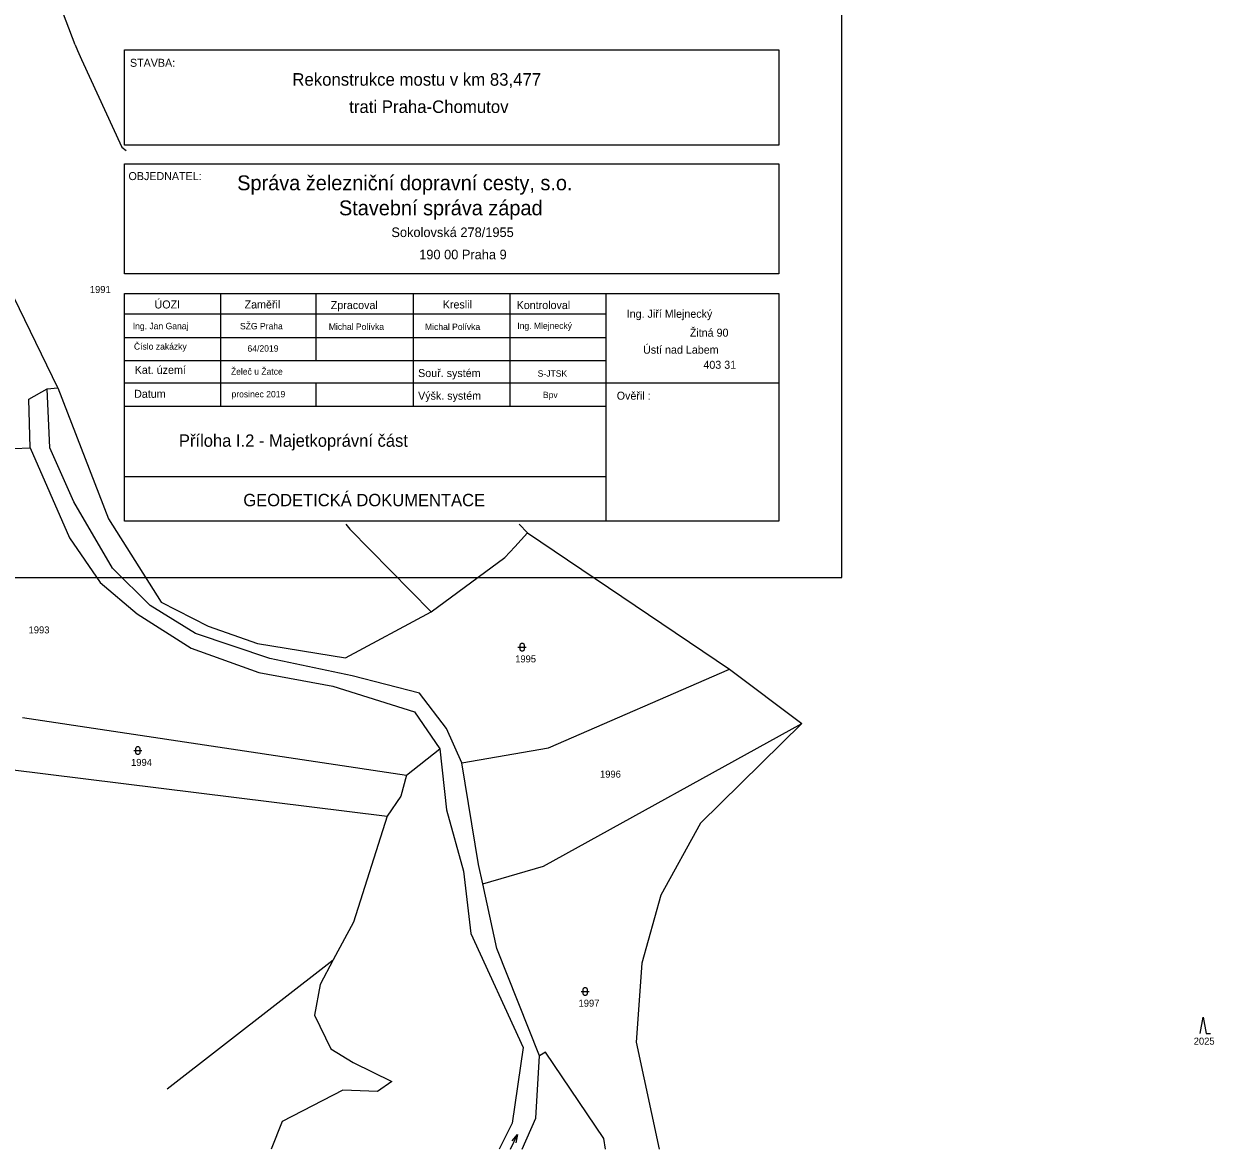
# Model space of a CAD drawing. Extents: x -801853 to -800578, y -1017479 to -1016338.
# Drawn here: x -800916.5 to -800627.9, y -1017477.7 to -1017204.8 of the extents above; entities that cross this region are included whole.
import ezdxf

# ---------------------------------------------------------------- set-up
doc = ezdxf.new("R2010")
doc.units = 0
for name, color, linetype in [('Default', 7, 'Continuous'), ('KN_HRANICE', 7, 'Continuous'), ('KN_KULTURY', 7, 'Continuous'), ('KN_PARCELY', 7, 'Continuous'), ('LEGENDA', 7, 'Continuous'), ('tabulka', 7, 'Continuous')]:
    doc.layers.add(name, color=color, linetype=linetype)

# ---------------------------------------------------------------- blocks, each defined once
blk = doc.blocks.new('308')
at = {"layer": 'Default'}
blk.add_lwpolyline([(-0.75, 0), (0, 4), (0.75, 0), (1.75, 0)], dxfattribs=at)
blk = doc.blocks.new('316')
at = {"layer": 'Default'}
for points in [[(-1, 1), (0.27, 1), (1, 1)], [(-0.5, 1.5), (-0.4, 1.79), (-0.15, 1.97), (0.16, 1.97), (0.41, 1.79), (0.51, 1.5), (0.51, 0.5), (0.41, 0.21), (0.16, 0.03), (-0.15, 0.03), (-0.4, 0.21), (-0.5, 0.5), (-0.5, 1.5)]]:
    blk.add_lwpolyline(points, dxfattribs=at)

msp = doc.modelspace()

# ---------------------------------------------------------------- linework, layer by layer
at = {"layer": 'KN_HRANICE'}
for p, q in [((-800904.03, -1017209.93), (-800916.2, -1017177.92)), ((-800904.03, -1017209.93), (-800903.5, -1017211.33)), ((-800903.5, -1017211.33), (-800902.5, -1017213.51)), ((-800902.5, -1017213.51), (-800892.76, -1017234.71)), ((-800892.76, -1017234.71), (-800891.71, -1017235.57)), ((-800908.25, -1017293.09), (-800925.53, -1017257.6)), ((-800915.3, -1017295.86), (-800910.8, -1017293.37)), ((-800910.8, -1017293.37), (-800908.25, -1017293.09)), ((-800910.14, -1017307.62), (-800910.8, -1017293.37)), ((-800908.25, -1017293.09), (-800895.98, -1017324.86)), ((-800914.93, -1017307.65), (-800915.3, -1017295.86)), ((-800925.36, -1017308.04), (-800914.93, -1017307.65)), ((-800914.93, -1017307.65), (-800905.45, -1017329.47)), ((-800904.4, -1017320.71), (-800910.14, -1017307.62)), ((-800894.96, -1017336.82), (-800904.4, -1017320.71)), ((-800895.98, -1017324.86), (-800883.2, -1017345.04)), ((-800838.41, -1017326.15), (-800837.42, -1017327.39)), ((-800837.42, -1017327.39), (-800817.72, -1017347.38)), ((-800797.47, -1017331.62), (-800794.33, -1017328.28)), ((-800796.41, -1017326.15), (-800794.33, -1017328.28)), ((-800794.33, -1017328.28), (-800745.35, -1017361.29)), ((-800905.45, -1017329.47), (-800897.94, -1017340.24)), ((-800817.72, -1017347.38), (-800799.89, -1017334.2)), ((-800799.89, -1017334.2), (-800797.47, -1017331.62)), ((-800885.82, -1017345.89), (-800894.96, -1017336.82)), ((-800897.94, -1017340.24), (-800888.98, -1017347.84)), ((-800874.85, -1017352.61), (-800885.82, -1017345.89)), ((-800883.2, -1017345.04), (-800871.81, -1017350.85)), ((-800888.98, -1017347.84), (-800875.89, -1017356.2)), ((-800838.46, -1017358.55), (-800817.72, -1017347.38)), ((-800871.81, -1017350.85), (-800859.86, -1017355.03)), ((-800856.81, -1017358.7), (-800874.85, -1017352.61)), ((-800875.89, -1017356.2), (-800859.52, -1017362.06)), ((-800859.86, -1017355.03), (-800838.46, -1017358.55)), ((-800836.88, -1017362.87), (-800856.81, -1017358.7)), ((-800859.52, -1017362.06), (-800841.58, -1017365.44)), ((-800820.52, -1017367.14), (-800836.88, -1017362.87)), ((-800789.24, -1017380.33), (-800745.35, -1017361.29)), ((-800745.35, -1017361.29), (-800727.83, -1017374.48)), ((-800841.58, -1017365.44), (-800821.72, -1017371.63)), ((-800814.02, -1017375.7), (-800820.52, -1017367.14)), ((-800821.72, -1017371.63), (-800815.6, -1017380.62)), ((-800916.78, -1017373.03), (-800823.68, -1017387.02)), ((-800790.52, -1017409.01), (-800727.83, -1017374.48)), ((-800727.83, -1017374.48), (-800752.41, -1017398.66)), ((-800810.29, -1017384.01), (-800814.02, -1017375.7)), ((-800823.68, -1017387.02), (-800815.6, -1017380.62)), ((-800815.6, -1017380.62), (-800814.01, -1017395.39)), ((-800810.29, -1017384.01), (-800789.24, -1017380.33)), ((-800920.37, -1017385.53), (-800828.38, -1017396.89)), ((-800806.21, -1017408.67), (-800810.29, -1017384.01)), ((-800823.68, -1017387.02), (-800825.04, -1017392.1)), ((-800825.04, -1017392.1), (-800828.38, -1017396.89)), ((-800828.38, -1017396.89), (-800836.59, -1017422.58)), ((-800814.01, -1017395.39), (-800809.89, -1017410.22)), ((-800752.41, -1017398.66), (-800762, -1017416.1)), ((-800805.21, -1017413.29), (-800806.21, -1017408.67)), ((-800805.21, -1017413.29), (-800790.52, -1017409.01)), ((-800809.89, -1017410.22), (-800808.14, -1017425.35)), ((-800801.79, -1017429.03), (-800805.21, -1017413.29)), ((-800762, -1017416.1), (-800766.63, -1017432.59)), ((-800836.59, -1017422.58), (-800841.46, -1017431.73)), ((-800808.14, -1017425.35), (-800795.44, -1017452.98)), ((-800791.46, -1017455.01), (-800801.79, -1017429.03)), ((-800881.75, -1017463.05), (-800841.46, -1017431.73)), ((-800841.46, -1017431.73), (-800844.67, -1017437.76)), ((-800766.63, -1017432.59), (-800768.04, -1017451.67)), ((-800844.67, -1017437.76), (-800846.03, -1017445.14)), ((-800846.03, -1017445.14), (-800842.06, -1017453.34)), ((-800768.04, -1017451.67), (-800762.46, -1017477.65)), ((-800842.06, -1017453.34), (-800836.67, -1017456.66)), ((-800795.44, -1017452.98), (-800798.1, -1017471.37)), ((-800792.36, -1017470.15), (-800791.46, -1017455.01)), ((-800789.98, -1017454.15), (-800791.46, -1017455.01)), ((-800775.83, -1017475.04), (-800789.98, -1017454.15)), ((-800836.67, -1017456.66), (-800827.29, -1017461.28)), ((-800827.29, -1017461.28), (-800830.74, -1017463.67)), ((-800839.17, -1017463.36), (-800853.88, -1017470.95)), ((-800830.74, -1017463.67), (-800839.17, -1017463.36)), ((-800853.88, -1017470.95), (-800856.51, -1017477.65)), ((-800798.1, -1017471.37), (-800801.22, -1017477.65)), ((-800795.67, -1017477.65), (-800792.36, -1017470.15)), ((-800775.45, -1017477.65), (-800775.83, -1017475.04))]:
    msp.add_line(p, q, dxfattribs=at)
at = {"layer": 'KN_KULTURY'}
msp.add_line((-800798.5, -1017477.65), (-800796.76, -1017474.07), dxfattribs=at)
msp.add_lwpolyline([(-800798.08, -1017475.65), (-800796.76, -1017474.07), (-800797.18, -1017476.09)], dxfattribs=at)
at = {"layer": 'LEGENDA'}
msp.add_lwpolyline([(-801559.16, -1017339.08), (-800718.16, -1017339.08), (-800718.16, -1016745.08), (-801559.16, -1016745.08)], close=True, dxfattribs=at)
at = {"layer": 'tabulka'}
for p, q in [((-800892.09, -1017270.25), (-800733.44, -1017270.25)), ((-800868.81, -1017270.25), (-800868.81, -1017297.57)), ((-800845.66, -1017270.25), (-800845.66, -1017286.45)), ((-800822.06, -1017270.25), (-800822.06, -1017297.57)), ((-800798.61, -1017270.25), (-800798.61, -1017297.57)), ((-800775.31, -1017325.38), (-800775.31, -1017270.25)), ((-800892.09, -1017275.16), (-800775.31, -1017275.16)), ((-800892.09, -1017280.87), (-800775.31, -1017280.87)), ((-800892.09, -1017286.45), (-800775.31, -1017286.45)), ((-800892.09, -1017291.87), (-800733.44, -1017291.87)), ((-800845.66, -1017291.87), (-800845.66, -1017297.57)), ((-800892.09, -1017297.57), (-800775.31, -1017297.57)), ((-800892.09, -1017314.56), (-800775.31, -1017314.56))]:
    msp.add_line(p, q, dxfattribs=at)
for points in [[(-800892.09, -1017211.16), (-800733.44, -1017211.16), (-800733.44, -1017234.23), (-800892.09, -1017234.23)], [(-800892.09, -1017238.75), (-800733.44, -1017238.75), (-800733.44, -1017265.44), (-800892.09, -1017265.44)]]:
    msp.add_lwpolyline(points, close=True, dxfattribs=at)
msp.add_lwpolyline([(-800733.44, -1017270.25), (-800733.44, -1017325.38), (-800892.09, -1017325.38), (-800892.09, -1017270.25)], dxfattribs=at)

# ---------------------------------------------------------------- block references
at = {"layer": 'KN_KULTURY'}
for name, p in [('316', (-800795.67, -1017356.95)), ('316', (-800888.84, -1017382.04)), ('316', (-800780.38, -1017440.41)), ('308', (-800630.53, -1017449.61))]:
    msp.add_blockref(name, p, dxfattribs=at)

# ---------------------------------------------------------------- texts
at = {"layer": 'KN_PARCELY'}
for s, p in [('1991', (-800900.48, -1017270.1)), ('1993', (-800915.33, -1017352.62)), ('1995', (-800797.35, -1017359.65)), ('1994', (-800890.48, -1017384.74)), ('1996', (-800776.78, -1017387.58)), ('1997', (-800781.98, -1017443.11)), ('2025', (-800632.82, -1017452.31))]:
    msp.add_text(s, height=1.7, dxfattribs=at).set_placement(p)
at = {"layer": 'tabulka'}
for s, height, p in [('STAVBA:', 1.94, (-800890.75, -1017215.27)), ('Rekonstrukce mostu v km 83,477', 3.04, (-800851.38, -1017219.85)), ('trati Praha-Chomutov', 3.04, (-800837.59, -1017226.46)), ('OBJEDNATEL:', 1.94, (-800891.1, -1017242.73)), ('Správa železniční dopravní cesty, s.o.', 3.61, (-800864.75, -1017245.2)), ('Stavební správa západ', 3.61, (-800840.08, -1017251.27)), ('Sokolovská 278/1955', 2.32, (-800827.36, -1017256.54)), ('190 00 Praha 9', 2.32, (-800820.62, -1017261.93)), ('ÚOZI', 1.94, (-800884.79, -1017273.85)), ('Zaměřil', 1.94, (-800862.96, -1017273.85)), ('Zpracoval', 1.94, (-800842.06, -1017274)), ('Kreslil', 1.94, (-800814.9, -1017273.85)), ('Kontroloval', 1.94, (-800796.99, -1017274)), ('Ing. Jiří Mlejnecký', 1.94, (-800770.3, -1017276.11)), ('Ing. Jan Ganaj', 1.552, (-800890.08, -1017278.88)), ('SŽG Praha', 1.552, (-800864.07, -1017278.91)), ('Michal Polívka', 1.552, (-800842.54, -1017279.04)), ('Michal Polívka', 1.552, (-800819.21, -1017279.07)), ('Ing. Mlejnecký', 1.552, (-800796.84, -1017278.81)), ('Žitná 90', 1.94, (-800755, -1017280.69)), ('Číslo zakázky', 1.552, (-800889.79, -1017283.83)), ('Ústí nad Labem', 1.94, (-800766.34, -1017284.81)), ('64/2019', 1.552, (-800862.25, -1017284.32)), ('Kat. území', 1.94, (-800889.6, -1017289.71)), ('Želeč u Žatce', 1.552, (-800866.27, -1017289.91)), ('403 31', 1.94, (-800751.71, -1017288.47)), ('Souř. systém', 1.94, (-800820.88, -1017290.48)), ('S-JTSK', 1.552, (-800791.89, -1017290.39)), ('Datum', 1.94, (-800889.74, -1017295.51)), ('prosinec 2019', 1.552, (-800866.13, -1017295.4)), ('Výšk. systém', 1.94, (-800820.89, -1017295.97)), ('Bpv', 1.552, (-800790.62, -1017295.58)), ('Ověřil :', 1.94, (-800772.72, -1017295.97)), ('Příloha I.2 - Majetkoprávní část', 3, (-800878.88, -1017307.38)), ('GEODETICKÁ DOKUMENTACE ', 3, (-800863.27, -1017321.79))]:
    msp.add_text(s, height=height, dxfattribs=at).set_placement(p)

doc.saveas('drawing.dxf')
